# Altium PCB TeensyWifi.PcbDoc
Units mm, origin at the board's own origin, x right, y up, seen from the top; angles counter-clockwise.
Board outline 127 x 134.37 mm, 2 copper layers (Top Layer, Bottom Layer); 33 components, 52 nets, 205 pads, 0 vias.
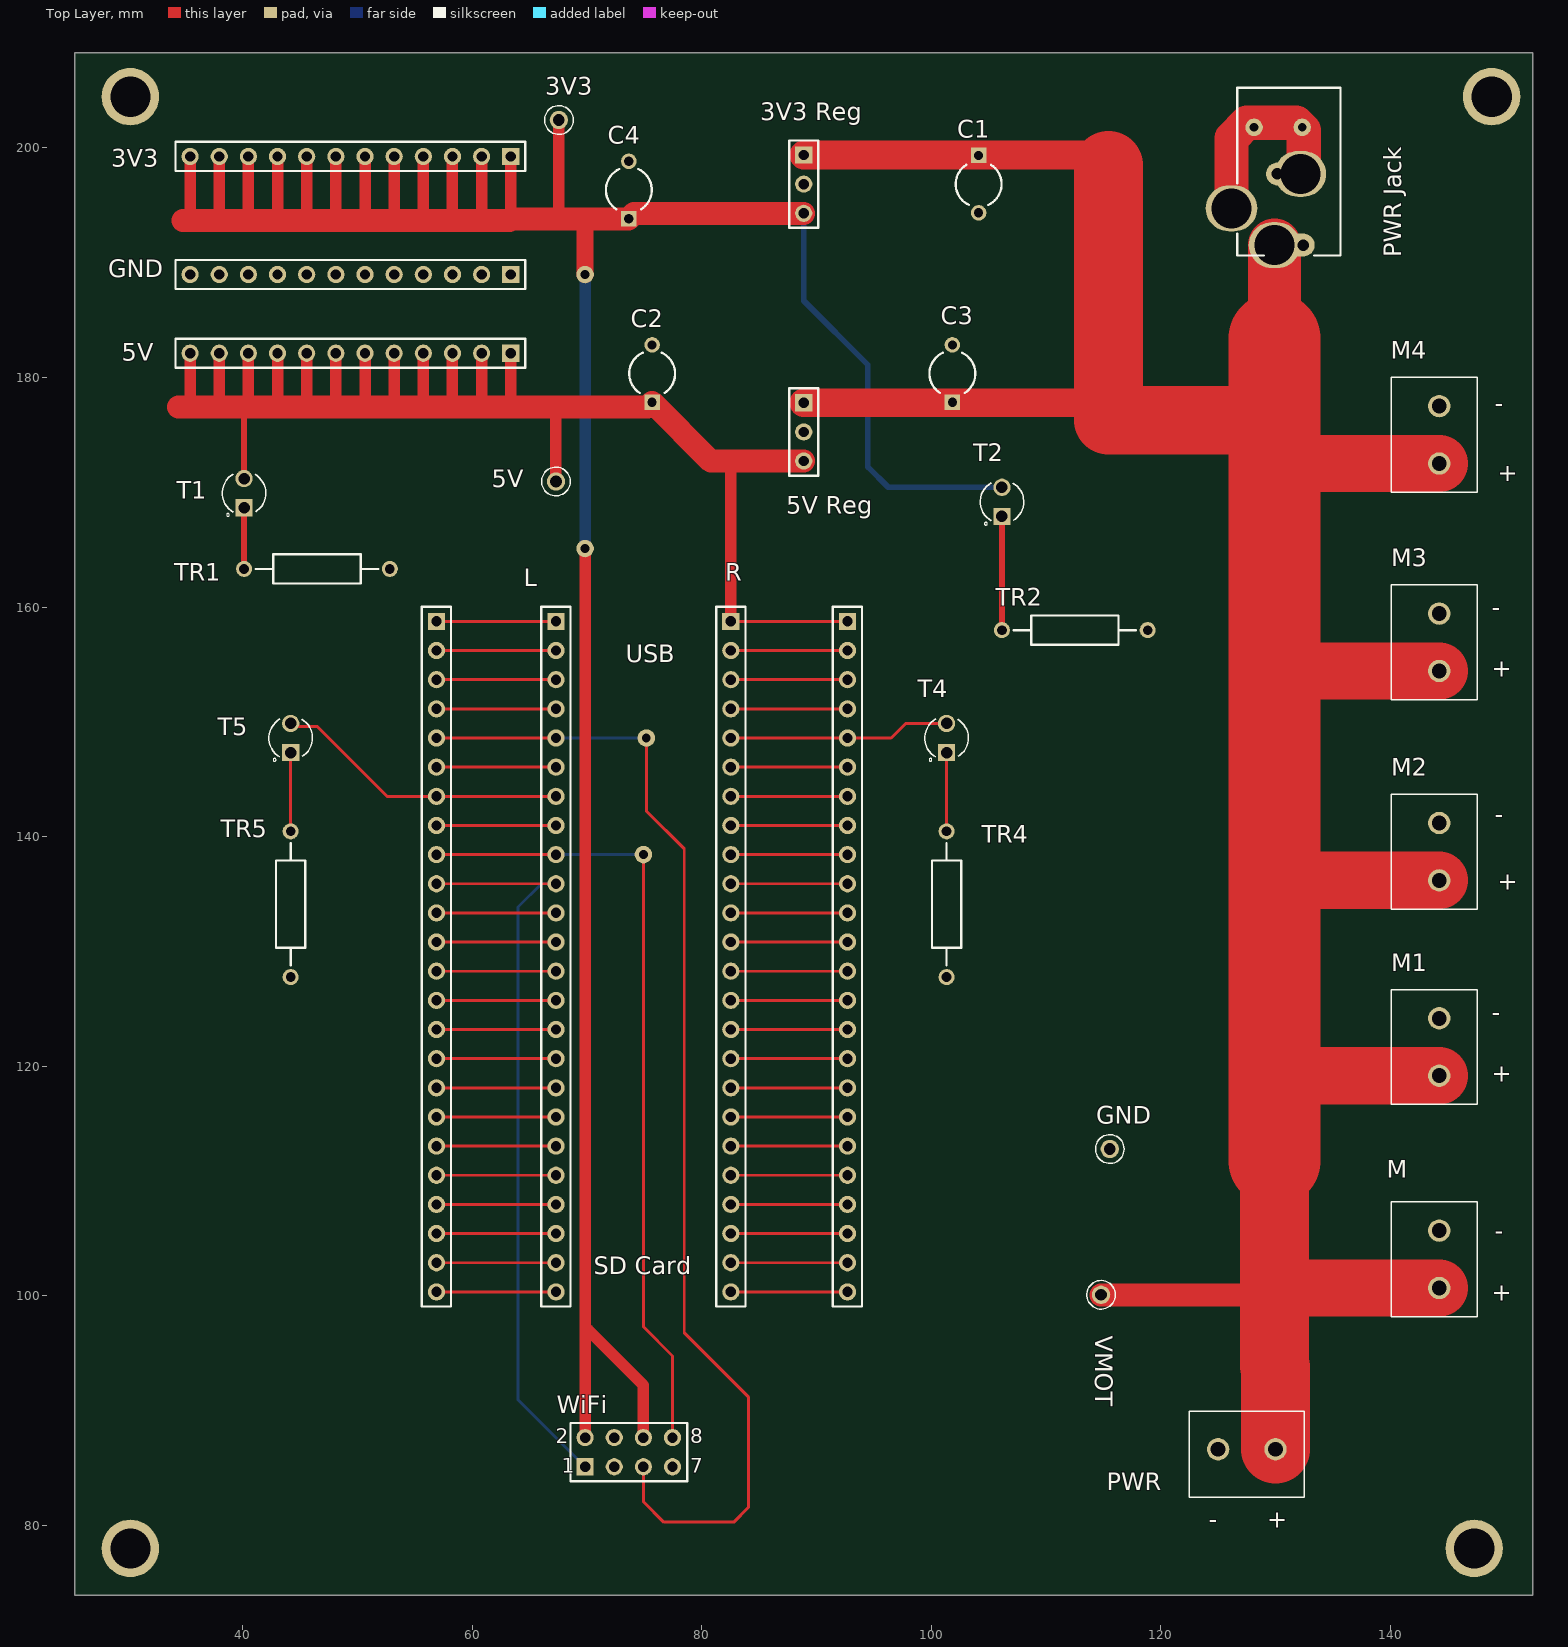
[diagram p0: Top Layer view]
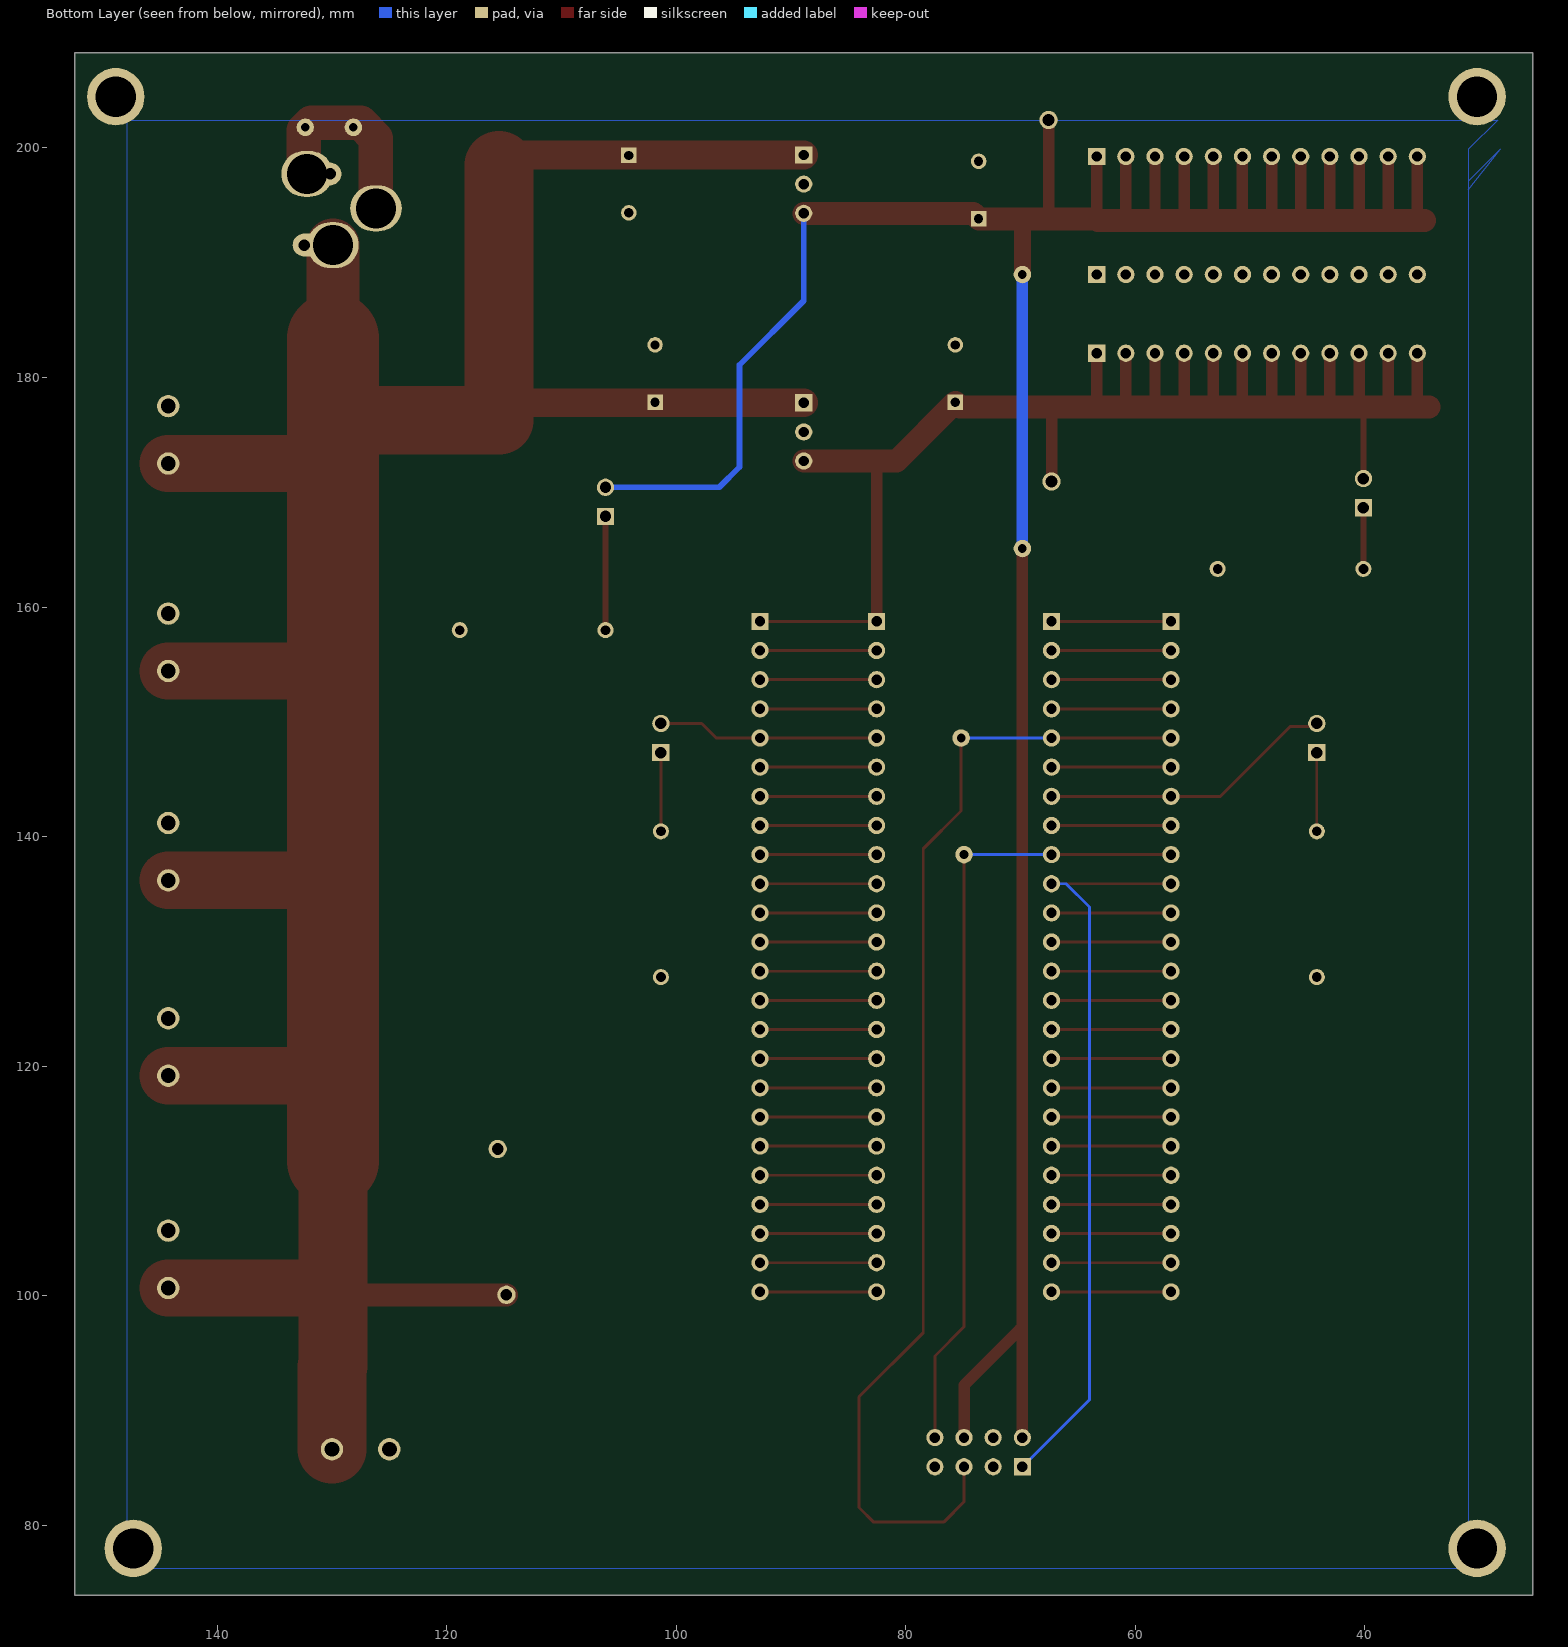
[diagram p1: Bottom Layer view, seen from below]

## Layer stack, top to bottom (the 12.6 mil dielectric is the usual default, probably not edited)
Top Solder: solder mask 0.0102, Solder Resist, Dk 3.5
Top Layer: signal copper 0.0356
Dielectric 1: dielectric 0.32, FR-4, Dk 4.8
Bottom Layer: signal copper 0.0356
Bottom Solder: solder mask 0.0102, Solder Resist, Dk 3.5

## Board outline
25.4,73.914 152.4,73.914 152.4,208.28 25.4,208.28

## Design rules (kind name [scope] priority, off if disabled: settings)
Clearance [All] p1: gap=0.254
PolygonConnect [All] p1: connectstyle=Relief reliefconductorwidth=0.254 reliefentries=4 polygonreliefangle="90 Angle" airgapwidth=0.254
RoutingVias [All] p1: holewidth=0.711 width=1.27 viastyle="Through Hole" minholewidth=0.711 minwidth=1.27 maxholewidth=0.711 maxwidth=1.27
SolderMaskExpansion [All] p1: expansion=0.102
Width [All] p1: maxlimit=0.254 minlimit=0.254 preferedwidth=5 minimp=50.000000 maximp=50.000000 favimp=50.000000
30 further rules are at their usual default settings.

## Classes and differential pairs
component class TeensyWifi: 3V3 "3V3 Reg" 5V "5V Reg" C1 C2 C3 C4 GND M M1 M2 M3 M4 PWR "PWR Jack" T1 T2 T4 T5 TR1 TR2 TR4 TR5

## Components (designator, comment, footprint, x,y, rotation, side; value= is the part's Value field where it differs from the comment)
3V3 "Header 12" HDR1X12 63.373,199.263 r180 top (schematic designator P3)
3V3 "" TPCW51D250H460P 67.564,202.438 r0 top (schematic designator TP2)
"3V3 Reg" "Header 2" HDR1X3 88.9,199.39 r270 top (schematic designator "Sw Reg2")
5V "Header 12" HDR1X12 63.373,182.118 r180 top (schematic designator P2)
5V "" TPCW51D250H460P 67.31,170.942 r0 top (schematic designator TP1)
"5V Reg" "Header 3" HDR1X3 88.9,177.8 r270 top (schematic designator "Sw Reg1")
C1 "Cap2" CAPR5-4X5 104.14,196.85 r270 top
C2 "Cap2" CAPR5-4X5 75.692,180.34 r90 top
C3 "Cap2" CAPR5-4X5 101.854,180.34 r90 top
C4 "Cap2" CAPR5-4X5 73.66,196.342 r90 top
GND "5003" TPCW51D250H460P 115.57,112.776 r0 top (schematic designator TP5)
GND "Header 12" HDR1X12 63.373,188.976 r180 top (schematic designator P1)
L "Header 24" HDR1X24 67.31,158.75 r270 top (schematic designator "Teensy L")
M "" 691102710002 144.272,103.164 r90 top (schematic designator J?)
M1 "" 691102710002 144.272,121.666 r90 top
M2 "" 691102710002 144.272,138.684 r90 top
M3 "" 691102710002 144.272,156.932 r90 top
M4 "" 691102710002 144.272,175.006 r90 top
PWR "" 691102710002 127.508,86.614 r180 top (schematic designator J1)
"PWR Jack" "PWR2.5" KLD-0202 131.175,205.239 r270 top (schematic designator "PWR Jack?")
R "Header 24" HDR1X24 82.55,158.75 r270 top (schematic designator "Teensy R")
T1 "LTL-1CHYE" LED_LTL-1CHYE_LTL-1CHYE(Primary) 40.132,169.926 r90 top
T2 "LTL-1CHYE" LED_LTL-1CHYE_LTL-1CHYE(Primary) 106.172,169.164 r90 top
T4 "LTL-1CHYE" LED_LTL-1CHYE_LTL-1CHYE(Primary) 101.346,148.59 r90 top
T5 "LTL-1CHYE" LED_LTL-1CHYE_LTL-1CHYE(Primary) 44.196,148.59 r90 top
"Teensy L1" "Header 24" HDR1X24 56.896,158.75 r270 top
"Teensy R1" "Header 24" HDR1X24 92.71,158.75 r270 top
TR1 "" AXIAL-0.5 46.482,163.322 r180 top
TR2 "" AXIAL-0.5 112.522,157.988 r180 top
TR4 "" AXIAL-0.5 101.346,134.112 r90 top
TR5 "" AXIAL-0.5 44.196,134.112 r90 top
VMOT "5003" TPCW51D250H460P 114.808,100.076 r0 top (schematic designator TP6)
WiFi "Header 4X2" HDR2X4 69.85,85.09 r0 top (schematic designator ESP)

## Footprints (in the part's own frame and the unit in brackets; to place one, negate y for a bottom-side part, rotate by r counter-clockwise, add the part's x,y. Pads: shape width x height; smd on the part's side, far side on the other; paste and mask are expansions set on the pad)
691102710002 [mm]
  round 1.95 hole 1.3: 1(-2.5,0) 2(2.5,0)
  silkscreen extent -5,-3.3 5,4.2
AXIAL-0.5 [mm] "Axial Device, Thru-Hole; 2 Leads; 0.5 in Pin Spacing"
  round 1.4 hole 0.85: 1(-6.35,0) 2(6.35,0)
  silkscreen extent -5.33,-1.27 5.33,1.27
CAPR5-4X5 [mm] "Capacitor; 2 Leads"
  rect 1.35x1.35 hole 0.8: 1(-2.5,0)
  round 1.35 hole 0.8: 2(2.5,0)
  silkscreen extent -1.69,-2 1.82,2
HDR1X3 [mm] "Connector; Header; 3 Position"
  rect 1.5x1.5 hole 0.9: 1(0,0)
  round 1.5 hole 0.9: 2(2.54,0) 3(5.08,0)
  silkscreen extent -1.27,-1.27 6.35,1.27
HDR1X12 [mm] "Connector; Header; 12 Position"
  rect 1.5x1.5 hole 0.9: 1(0,0)
  round 1.5 hole 0.9: 2(2.54,0) 3(5.08,0) 4(7.62,0) 5(10.16,0) 6(12.7,0) 7(15.24,0) 8(17.78,0) 9(20.32,0) 10(22.86,0) 11(25.4,0) 12(27.94,0)
  silkscreen extent -1.27,-1.27 29.21,1.27
HDR1X24 [mm] "Connector; Header; 24 Position"
  rect 1.5x1.5 hole 0.9: 1(0,0)
  round 1.5 hole 0.9: 2(2.54,0) 3(5.08,0) 4(7.62,0) 5(10.16,0) 6(12.7,0) 7(15.24,0) 8(17.78,0) 9(20.32,0) 10(22.86,0) 11(25.4,0) 12(27.94,0) 13(30.48,0) 14(33.02,0) 15(35.56,0) 16(38.1,0) 17(40.64,0) 18(43.18,0) 19(45.72,0) 20(48.26,0) 21(50.8,0) 22(53.34,0) 23(55.88,0) 24(58.42,0)
  silkscreen extent -1.27,-1.27 59.69,1.27
HDR2X4 [mm] "Connector; Header; 4x2 Position"
  rect 1.5x1.5 hole 0.9: 1(0,0)
  round 1.5 hole 0.9: 2(0,2.54) 3(2.54,0) 4(2.54,2.54) 5(5.08,0) 6(5.08,2.54) 7(7.62,0) 8(7.62,2.54)
  silkscreen extent -1.27,-1.27 8.89,3.81
KLD-0202 [mm] "DC Power Jack, 2.5mm, KLD Series, PCB Mount"
  oval 2x4.5 all layers, no hole: 1(13.7,0)
  oval 4x4.5 hole 3.5: 1A(13.7,-1.25) 2B(7.5,1) 3(10.5,-5)
  round 1.5 hole 1: 1B(13.7,1.25) 2A(7.5,-1) 3A(9.5,-5) 3B(11.5,-5)
  oval 2x4 all layers, no hole: 2(7.5,0)
  silkscreen extent 0,-4.5 14.6,4.5
LED_LTL-1CHYE_LTL-1CHYE(Primary) [mm]
  round 1.508 hole 1: A(1.27,0)
  rect 1.508x1.508 hole 1: C(-1.27,0)
  silkscreen extent -2.03,-1.9 1.66,1.9
TPCW51D250H460P [mm]
  round 1.6 hole 1.02: 1(0,0)
  silkscreen extent -1.25,-1.25 1.25,1.25

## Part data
3V3 5V GND: "Header, 12-Pin"
3V3 5V: library part 5003, "Test Point; Orange; Thru-Hole; Snap-Fit; SilverPlate; 0.040 in. Dia.; 0.300 In."
"3V3 Reg": library part "Header 3", "Header, 3-Pin"
"5V Reg": "Header, 3-Pin"
C1 C2 C3 C4: "Capacitor"
GND VMOT: "Test Point; Orange; Thru-Hole; Snap-Fit; SilverPlate; 0.040 in. Dia.; 0.300 In."
L R "Teensy L1" "Teensy R1": "Header, 24-Pin"
M M1 M2 M3 M4 PWR: library part 691102710002, "102 Series 5mm Pitch Straight, PCB Terminal Block, Through Hole, 2 Way"
"PWR Jack": "Low Voltage Power Supply Connector"
T1 T2 T4 T5: "Yellow 3.1 mm 45° Tinted Clear 40 mcd 2.1 V LED Through Hole"
TR1 TR2 TR4 TR5: library part "Res Semi", "Semiconductor Resistor"
WiFi: "Header, 4-Pin, Dual row"

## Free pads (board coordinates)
  round 1.524 hole 0.762: 2(132.334,201.803) 3(128.143,201.803) 4(69.85,188.976) 9(69.85,165.1) 10(74.93,138.43) 11(75.184,148.59)
  round 5 hole 3.5: 5(148.844,204.47) 6(30.226,204.47) 7(30.226,77.978) 8(147.32,77.978)

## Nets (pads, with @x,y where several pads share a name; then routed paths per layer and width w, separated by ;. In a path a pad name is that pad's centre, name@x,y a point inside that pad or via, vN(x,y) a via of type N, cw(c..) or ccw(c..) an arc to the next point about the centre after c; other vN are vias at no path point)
0: "Teensy L1.2" L.2 | length 10.4
  Top Layer w0.254: 56.896,156.21 L.2
1: "Teensy L1.3" L.3 | length 10.4
  Top Layer w0.254: 56.896,153.67 L.3
2: "Teensy L1.4" L.4 | length 10.4
  Top Layer w0.254: 56.896,151.13 L.4
3V3: 3V3.1 3V3.2 3V3.3 3V3.4 3V3.5 3V3.6 3V3.7 3V3.8 3V3.9 3V3.10 3V3.11 3V3.12 "3V3 Reg.3" C4.1 pad.4 pad.9 T2.A WiFi.2 WiFi.6 | length 285.2
  Top Layer w0.254: 34.798,193.675 35.433,194.31 ; 42.926,193.675 43.053,193.802 ; 45.466,193.675 45.593,193.802 ; 48.006,193.675 48.133,193.802 ; 53.086,193.675 53.213,193.802 ; 55.626,193.675 55.753,193.802 ; 60.706,193.675 60.833,193.802 ; 63.246,193.675 63.373,193.802 ; 69.85,97.028 70.104,97.028 ; C4.1@73.62,193.802 C4.1
  Top Layer w1: 35.433,194.31 3V3.12 ; 37.973,193.675 3V3.11 ; 40.513,193.675 3V3.10 ; 43.053,193.802 3V3.9 ; 45.593,193.802 3V3.8 ; 48.133,193.802 3V3.7 ; 50.673,193.675 3V3.6 ; 53.213,193.802 3V3.5 ; 55.753,193.802 3V3.4 ; 58.293,193.675 3V3.3 ; 60.833,193.802 3V3.2 ; 63.373,193.802 3V3.1@63.373,199.263 ; 67.564,193.802 3V3.1@67.564,202.438 ; WiFi.2 69.85,97.028 pad.9 ; 70.104,97.028 74.93,92.202 WiFi.6
  Top Layer w1.5: pad.4 69.85,193.802
  Top Layer w2: 34.798,193.675 37.973,193.675 40.513,193.675 42.926,193.675 45.466,193.675 48.006,193.675 50.673,193.675 53.086,193.675 55.626,193.675 58.293,193.675 60.706,193.675 63.246,193.675 ; 63.373,193.802 67.564,193.802 69.85,193.802 C4.1@73.62,193.802 ; C4.1 74.128,194.31 88.9,194.31
  Bottom Layer w0.5: 88.9,194.31 88.9,186.69 94.488,181.102 94.488,172.212 96.266,170.434 T2.A
  Bottom Layer w1: pad.9 pad.4
5: "Teensy L1.7" L.7 T5.A | length 25.7
  Top Layer w0.254: T5.A 44.45,149.606 46.482,149.606 52.578,143.51 56.896,143.51 L.7
5V: 5V.1 5V.2 5V.3 5V.4 5V.5 5V.6 5V.7 5V.8 5V.9 5V.10 5V.11 5V.12 "5V Reg.3" "Teensy R1.1" C2.1 R.1 T1.A | length 150.7
  Top Layer w0.254: 34.417,177.419 35.433,178.435 ; 37.846,177.419 37.973,177.546 ; 40.132,177.038 40.513,177.419 ; 45.593,177.546 45.72,177.419 ; 48.006,177.419 48.133,177.546 ; C2.1@75.271,177.419 C2.1 ; R.1 92.71,158.75
  Top Layer w0.5: T1.A 40.132,177.038
  Top Layer w1: 35.433,178.435 5V.12 ; 37.973,177.546 5V.11 ; 40.513,177.419 5V.10 ; 43.053,177.419 5V.9 ; 45.593,177.546 5V.8 ; 48.133,177.546 5V.7 ; 50.673,177.419 5V.6 ; 53.213,177.419 5V.5 ; 55.753,177.419 5V.4 ; 58.293,177.419 5V.3 ; 60.833,177.419 5V.2 ; 63.373,177.419 5V.1@63.373,182.118 ; 5V.1@67.31,170.942 67.31,177.419 ; R.1 82.55,172.72
  Top Layer w2: 34.417,177.419 37.846,177.419 40.513,177.419 43.053,177.419 45.72,177.419 48.006,177.419 50.673,177.419 53.213,177.419 55.753,177.419 58.293,177.419 60.833,177.419 63.373,177.419 67.31,177.419 C2.1@75.271,177.419 ; C2.1 80.812,172.72 82.55,172.72 88.9,172.72
6: "Teensy L1.8" L.8 | length 10.4
  Top Layer w0.254: 56.896,140.97 L.8
9: "Teensy L1.11" L.11 | length 10.4
  Top Layer w0.254: 56.896,133.35 L.11
10: "Teensy L1.12" L.12 | length 10.4
  Top Layer w0.254: 56.896,130.81 L.12
12: "Teensy L1.14" L.14 | length 10.4
  Top Layer w0.254: 56.896,125.73 L.14
16: "Teensy R1.11" R.11 | length 10.2
  Top Layer w0.254: R.11 92.71,133.35
21: "Teensy R1.6" R.6 | length 10.2
  Top Layer w0.254: R.6 92.71,146.05
22: "Teensy R1.5" R.5 T4.A | length 19.3
  Top Layer w0.254: R.5 92.71,148.59 96.52,148.59 97.79,149.86 T4.A
23: "Teensy R1.4" R.4 | length 10.2
  Top Layer w0.254: R.4 92.71,151.13
24: "Teensy L1.16" L.16 | length 10.4
  Top Layer w0.254: 56.896,120.65 L.16
25: "Teensy L1.17" L.17 | length 10.4
  Top Layer w0.254: 56.896,118.11 L.17
26: "Teensy L1.18" L.18 | length 10.4
  Top Layer w0.254: 56.896,115.57 L.18
27: "Teensy L1.19" L.19 | length 10.4
  Top Layer w0.254: 56.896,113.03 L.19
28: "Teensy L1.20" L.20 | length 10.4
  Top Layer w0.254: 56.896,110.49 L.20
29: "Teensy L1.21" L.21 | length 10.4
  Top Layer w0.254: 56.896,107.95 L.21
30: "Teensy L1.22" L.22 | length 10.4
  Top Layer w0.254: 56.896,105.41 L.22
32: "Teensy L1.24" L.24 | length 10.4
  Top Layer w0.254: 56.896,100.33 L.24
33: "Teensy R1.24" R.24 | length 10.2
  Top Layer w0.254: R.24 92.71,100.33
34: "Teensy R1.23" R.23 | length 10.2
  Top Layer w0.254: R.23 92.71,102.87
35: "Teensy R1.22" R.22 | length 10.2
  Top Layer w0.254: R.22 92.71,105.41
37: "Teensy R1.20" R.20 | length 10.2
  Top Layer w0.254: R.20 92.71,110.49
38: "Teensy R1.19" R.19 | length 10.2
  Top Layer w0.254: R.19 92.71,113.03
39: "Teensy R1.18" R.18 | length 10.2
  Top Layer w0.254: R.18 92.71,115.57
A21: "Teensy R1.17" R.17 | length 10.2
  Top Layer w0.254: R.17 92.71,118.11
A22: "Teensy R1.16" R.16 | length 10.2
  Top Layer w0.254: R.16 92.71,120.65
CS1: "Teensy R1.7" R.7 | length 10.2
  Top Layer w0.254: R.7 92.71,143.51
CS2: "Teensy R1.8" R.8 | length 10.2
  Top Layer w0.254: R.8 92.71,140.97
CS3: "Teensy R1.9" R.9 | length 10.2
  Top Layer w0.254: R.9 92.71,138.43
CS4: "Teensy R1.10" R.10 | length 10.2
  Top Layer w0.254: R.10 92.71,135.89
DIR: "Teensy L1.6" L.6 | length 10.4
  Top Layer w0.254: 56.896,146.05 L.6
ENA1: "Teensy R1.12" R.12 | length 10.2
  Top Layer w0.254: R.12 92.71,130.81
ENA2: "Teensy R1.13" R.13 | length 10.2
  Top Layer w0.254: R.13 92.71,128.27
ENA3: "Teensy R1.21" R.21 | length 10.2
  Top Layer w0.254: R.21 92.71,107.95
ENA4: "Teensy L1.23" L.23 | length 10.4
  Top Layer w0.254: 56.896,102.87 L.23
GND: "3V3 Reg.2" "5V Reg.2" "PWR Jack.2" "PWR Jack.2A" "PWR Jack.2B" "PWR Jack.3" "PWR Jack.3A" "PWR Jack.3B" "Teensy L1.1" "Teensy R1.2" "Teensy R1.15" C1.2 C2.2 C3.2 C4.2 GND.1 GND.2 GND.3 GND.4 GND.5 GND.6 GND.7 GND.8 GND.9 GND.10 GND.11 GND.12 L.1 M1.2 M2.2 M3.2 M4.2 M.2 pad.2 pad.3 PWR.2 R.2 R.15 TR1.1 TR2.1 TR4.1 TR5.1 WiFi.7 | length 48.3
  Top Layer w0.254: 56.896,158.75 L.1 ; R.15 92.71,123.19 ; R.2 92.71,156.21 ; 126.175,194.739 126.175,195.739 ; 131.175,197.739 132.461,199.025
  Top Layer w3: 126.175,195.739 126.175,200.851 127.508,202.184 131.826,202.184 132.461,201.549 132.461,199.025
NetT1_C: T1.C TR1.2 | length 5.3
  Top Layer w0.5: TR1.2 T1.C
NetT2_C: T2.C TR2.2 | length 9.9
  Top Layer w0.5: TR2.2 T2.C
NetT4_C: T4.C TR4.2 | length 6.9
  Top Layer w0.254: TR4.2 T4.C
NetT5_C: T5.C TR5.2 | length 6.9
  Top Layer w0.254: TR5.2 T5.C
PIN3: "Teensy L1.5" L.5 pad.11 WiFi.5 | length 102.5
  Top Layer w0.254: 56.896,148.59 L.5 ; WiFi.5 74.93,82.042 76.708,80.264 82.804,80.264 84.074,81.534 84.074,91.186 78.486,96.774 78.486,138.938 75.184,142.24 pad.11
  Bottom Layer w0.254: L.5 pad.11
PIN3V3: "Teensy R1.3" R.3 | length 10.2
  Top Layer w0.254: R.3 92.71,153.67
PIN7: "Teensy L1.9" L.9 pad.10 WiFi.8 | length 69.9
  Top Layer w0.254: 56.896,138.43 L.9 ; pad.10 74.93,97.282 77.47,94.742 WiFi.8
  Bottom Layer w0.254: L.9 pad.10
PIN8: "Teensy L1.10" L.10 WiFi.1 | length 65.7
  Top Layer w0.254: 56.896,135.89 L.10
  Bottom Layer w0.254: L.10 66.04,135.89 64.008,133.858 64.008,90.932 WiFi.1
PINX: "Teensy L1.15" L.15 | length 10.4
  Top Layer w0.254: 56.896,123.19 L.15
SCK: "Teensy R1.14" R.14 | length 10.2
  Top Layer w0.254: R.14 92.71,125.73
SDA: "Teensy L1.13" L.13 | length 10.4
  Top Layer w0.254: 56.896,128.27 L.13
VMOT: "3V3 Reg.1" "5V Reg.1" "PWR Jack.1" "PWR Jack.1A" "PWR Jack.1B" C1.1 C3.1 M1.1 M2.1 M3.1 M4.1 M.1 PWR.1 VMOT.1 | length 292.8
  Top Layer w0.254: C3.1@101.814,177.8 C3.1 C3.1@101.894,177.8 ; C1.1@104.1,199.39 C1.1 C1.1@104.18,199.39 ; 113.919,177.8 115.443,176.276 ; 114.554,199.39 115.443,198.501 ; 128.909,100.076 129.925,101.092 130.353,100.664 ; 129.925,93.857 130.008,93.774 ; 129.925,119.38 130.139,119.166 ; 129.925,129.794 132.465,127.254 ; 129.925,134.62 131.489,136.184 ; 129.925,176.276 133.695,172.506 ; 130.052,124.714 129.925,124.587 132.338,122.174
  Top Layer w2: VMOT.1 128.909,100.076
  Top Layer w2.5: 88.9,177.8 C3.1@101.814,177.8 ; 88.9,199.39 C1.1@104.1,199.39 ; C3.1@101.894,177.8 113.919,177.8 ; C1.1@104.18,199.39 114.554,199.39
  Top Layer w4.6: 129.925,183.388 129.925,191.539
  Top Layer w5: 129.925,154.432 M3.1 ; 130.139,119.166 M1.1 ; 130.353,100.664 M.1 ; 131.489,136.184 M2.1 ; 133.695,172.506 M4.1
  Top Layer w6: 115.443,198.501 115.443,176.276 129.925,176.276 ; 129.925,93.857 129.925,101.092 129.925,111.76 ; PWR.1 130.008,93.774
  Top Layer w8: 129.925,111.76 129.925,119.38 129.925,124.587 129.925,129.794 129.925,134.62 129.925,154.432 129.925,176.276 129.925,183.388
pads on no net: WiFi.3 WiFi.4

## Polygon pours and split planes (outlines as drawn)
GND on Bottom Layer "GND" (solid, shelved, pour order 2): 28.194,199.898 30.988,197.104 30.988,76.2 148.59,76.2 149.098,76.708 147.828,77.978 147.828,202.438 28.448,202.438 30.988,199.898 30.988,196.342

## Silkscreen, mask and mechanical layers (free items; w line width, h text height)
Top Overlay:
  text "-" at 149.098,177.038 h1.52
  text "+" at 149.352,170.942 h1.52
  text "-" at 148.844,159.258 h1.52
  text "USB" at 73.406,155.194 h1.52
  text "+" at 148.844,153.924 h1.52
  text "-" at 149.098,141.224 h1.52
  text "+" at 149.352,135.382 h1.52
  text "-" at 148.844,123.952 h1.52
  text "+" at 148.844,118.618 h1.52
  text "-" at 149.098,104.902 h1.52
  text "SD Card" at 70.612,101.854 h1.52
  text "+" at 148.844,99.568 h1.52
  text "-" at 124.206,79.756 h1.52
  text "+" at 129.286,79.756 h1.52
